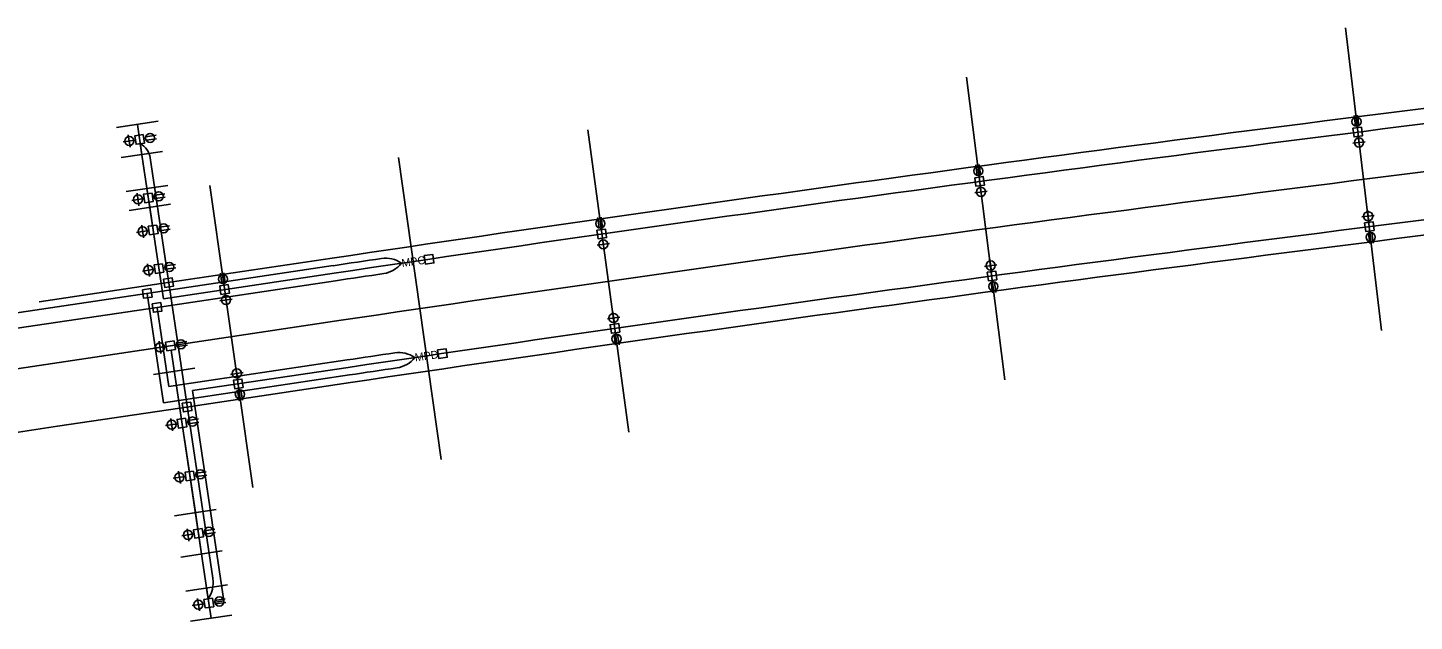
# Model space of a CAD drawing. Extents: x 927222 to 928611, y 636651 to 637029.
# Drawn here: x 927719.3 to 927901.3, y 636687 to 636764.9 of the extents above; entities that cross this region are included whole.
import ezdxf

# ---------------------------------------------------------------- set-up
doc = ezdxf.new("R2010")
doc.units = 0
for name, color, linetype in [('ActivePointCell_dp', 7, 'Continuous'), ('Miscellaneous2', 7, 'Continuous'), ('NonPlottingEle_dp', 7, 'Continuous'), ('PoleLight', 7, 'Continuous'), ('TextLabel', 7, 'Continuous')]:
    doc.layers.add(name, color=color, linetype=linetype)

msp = doc.modelspace()

# ---------------------------------------------------------------- linework, layer by layer
at = {"layer": 'ActivePointCell_dp'}
for p, q in [((927732.23, 636743.41), (927737.67, 636744.22)), ((927735.81, 636719.43), (927741.25, 636720.24)), ((927739.39, 636695.44), (927744.83, 636696.26))]:
    msp.add_line(p, q, dxfattribs=at)
at = {"layer": 'Miscellaneous2'}
for p, q in [((927896.95, 636725.18), (927892.24, 636764.9)), ((927847.53, 636718.73), (927842.5, 636758.41)), ((927730.97, 636751.82), (927736.41, 636752.63)), ((927734.29, 636748.27), (927733.69, 636752.22)), ((927798.17, 636711.86), (927792.81, 636751.5)), ((927731.57, 636747.86), (927737, 636748.67)), ((927773.54, 636708.27), (927767.96, 636747.88)), ((927735.32, 636741.35), (927734.95, 636743.82)), ((927748.86, 636704.6), (927743.19, 636744.19)), ((927732.6, 636740.94), (927738.04, 636741.75)), ((927735.32, 636741.35), (927736.2, 636735.41)), ((927738.03, 636723.17), (927760.44, 636726.52)), ((927738.03, 636723.17), (927760.44, 636726.52)), ((927641.76, 636708.8), (927738.03, 636723.17)), ((927641.76, 636708.8), (927738.03, 636723.17)), ((927741.3, 636701.29), (927739.86, 636710.93)), ((927738.58, 636700.88), (927744.02, 636701.7)), ((927742.11, 636695.85), (927741.3, 636701.29)), ((927740.06, 636690.99), (927745.5, 636691.81)), ((927743.37, 636687.44), (927742.78, 636691.4)), ((927740.65, 636687.04), (927746.09, 636687.85))]:
    msp.add_line(p, q, dxfattribs=at)
msp.add_arc((928647.64, 630784.89), 6007.5, 96.980509, 98.492547, dxfattribs=at)
msp.add_arc((928647.64, 630784.89), 6007.5, 96.980509, 98.492547, dxfattribs=at)
at = {"layer": 'NonPlottingEle_dp'}
for p, q in [((927734.07, 636749.69), (927737.11, 636729.35)), ((927735.36, 636747.85), (927743.6, 636692.67)), ((927736.81, 636731.33), (927759.23, 636734.68)), ((927736.96, 636730.34), (927759.37, 636733.69)), ((927737.11, 636729.35), (927759.52, 636732.7)), ((927720.79, 636728.94), (927736.81, 636731.33)), ((927736.27, 636728.22), (927759.67, 636731.71)), ((927640.69, 636715.97), (927736.96, 636730.34)), ((927734.98, 636730.05), (927737.13, 636715.71)), ((927640.98, 636713.99), (927736.27, 636728.22)), ((927736.27, 636728.22), (927737.82, 636717.83)), ((927738.12, 636722.62), (927742.99, 636689.98)), ((927737.82, 636717.83), (927761.22, 636721.33)), ((927740.93, 636717.29), (927761.37, 636720.34)), ((927737.13, 636715.71), (927761.51, 636719.35)), ((927739.25, 636715.01), (927761.66, 636718.36)), ((927740.93, 636717.29), (927745.05, 636689.72)), ((927723.22, 636712.62), (927739.25, 636715.01)), ((927642.98, 636700.64), (927723.22, 636712.62)), ((927743.63, 636689.5), (927745.05, 636689.72))]:
    msp.add_line(p, q, dxfattribs=at)
for centre, radius, start, end in [((928647.64, 630784.89), 6015.75, 96.980509, 98.492547), ((928647.64, 630784.89), 6013.75, 96.980509, 98.492547), ((927732.87, 636747.48), 2.52, 8.4925, 61.3837), ((928647.64, 630784.89), 6001.25, 96.980509, 98.492547), ((928647.64, 630784.89), 5999.25, 96.980509, 98.492547), ((928647.64, 630784.89), 6014.75, 98.431328, 98.492547), ((927766.26, 636731.03), 3.64, 54.9427, 98.4313), ((928647.64, 630784.89), 6012.75, 98.431325, 98.492547), ((927765.49, 636736.26), 3.64, 278.4313, 321.9148), ((928647.64, 630784.89), 6002.25, 98.432344, 98.492547), ((927768.01, 636718.65), 3.64, 54.9427, 98.6782), ((927767.23, 636723.88), 3.64, 278.4322, 321.9148), ((928647.64, 630784.89), 6000.25, 98.432192, 98.492547), ((927739.84, 636692.1), 3.8, 325.9435, 8.4925)]:
    msp.add_arc(centre, radius, start, end, dxfattribs=at)
at = {"layer": 'PoleLight'}
for p, q in [((927893.35, 636753.38), (927893.52, 636752.02)), ((927893.8, 636753.44), (927893.96, 636752.07)), ((927732.5, 636750.85), (927732.74, 636749.23)), ((927736.14, 636750.79), (927734.78, 636750.59)), ((927893.77, 636751.78), (927893.74, 636752)), ((927893.91, 636750.66), (927894.11, 636749.03)), ((927733.43, 636750.16), (927731.81, 636749.92)), ((927734.55, 636750.33), (927734.77, 636750.36)), ((927736.2, 636750.35), (927734.85, 636750.15)), ((927893.19, 636749.75), (927894.82, 636749.95)), ((927843.7, 636746.9), (927843.88, 636745.53)), ((927844.14, 636745.3), (927844.11, 636745.52)), ((927844.15, 636746.96), (927844.33, 636745.59)), ((927843.57, 636743.26), (927845.2, 636743.47)), ((927844.28, 636744.18), (927844.49, 636742.55)), ((927734.58, 636742.5), (927732.95, 636742.26)), ((927733.64, 636743.19), (927733.89, 636741.56)), ((927735.69, 636742.66), (927735.91, 636742.7)), ((927737.28, 636743.13), (927735.92, 636742.93)), ((927737.35, 636742.68), (927735.99, 636742.48)), ((927794.11, 636740), (927794.3, 636738.64)), ((927794.55, 636740.06), (927794.74, 636738.7)), ((927896.01, 636740.28), (927894.38, 636740.08)), ((927895.3, 636739.36), (927895.1, 636740.99)), ((927735.21, 636738.3), (927733.58, 636738.05)), ((927734.27, 636738.99), (927734.51, 636737.36)), ((927736.32, 636738.46), (927736.54, 636738.49)), ((927737.91, 636738.93), (927736.55, 636738.72)), ((927737.98, 636738.48), (927736.62, 636738.28)), ((927794.56, 636738.4), (927794.53, 636738.63)), ((927895.41, 636736.59), (927895.25, 636737.95)), ((927895.44, 636738.25), (927895.46, 636738.02)), ((927895.86, 636736.64), (927895.69, 636738.01)), ((927794.01, 636736.36), (927795.64, 636736.59)), ((927794.71, 636737.29), (927794.94, 636735.66)), ((927845.77, 636732.9), (927845.55, 636734.53)), ((927735.96, 636733.23), (927734.34, 636732.98)), ((927735.03, 636733.92), (927735.27, 636732.29)), ((927737.08, 636733.39), (927737.3, 636733.43)), ((927738.67, 636733.86), (927737.31, 636733.65)), ((927738.73, 636733.41), (927737.37, 636733.21)), ((927744.58, 636732.71), (927744.78, 636731.35)), ((927745.03, 636732.77), (927745.23, 636731.41)), ((927846.47, 636733.82), (927844.84, 636733.6)), ((927745.04, 636731.11), (927745.01, 636731.34)), ((927845.91, 636730.12), (927845.73, 636731.48)), ((927845.91, 636731.78), (927845.94, 636731.56)), ((927846.35, 636730.18), (927846.17, 636731.54)), ((927744.51, 636729.07), (927746.14, 636729.31)), ((927745.21, 636730), (927745.44, 636728.37)), ((927796.29, 636726.02), (927796.06, 636727.64)), ((927796.99, 636726.94), (927795.36, 636726.72)), ((927736.54, 636723.78), (927736.78, 636722.15)), ((927740.18, 636723.72), (927738.82, 636723.52)), ((927796.45, 636723.24), (927796.26, 636724.6)), ((927796.45, 636724.9), (927796.48, 636724.68)), ((927796.9, 636723.31), (927796.71, 636724.67)), ((927737.48, 636723.09), (927735.85, 636722.85)), ((927738.59, 636723.25), (927738.81, 636723.29)), ((927740.25, 636723.27), (927738.89, 636723.07)), ((927746.86, 636718.74), (927746.62, 636720.37)), ((927747.55, 636719.67), (927745.92, 636719.43)), ((927747.04, 636715.97), (927746.84, 636717.33)), ((927747.02, 636717.63), (927747.05, 636717.4)), ((927747.48, 636716.03), (927747.28, 636717.39)), ((927738.99, 636712.95), (927737.36, 636712.71)), ((927738.06, 636713.64), (927738.3, 636712.02)), ((927740.1, 636713.12), (927740.33, 636713.15)), ((927741.69, 636713.58), (927740.34, 636713.38)), ((927741.76, 636713.14), (927740.4, 636712.93)), ((927740.02, 636706.03), (927738.4, 636705.79)), ((927739.09, 636706.72), (927739.33, 636705.09)), ((927741.14, 636706.19), (927741.36, 636706.23)), ((927742.73, 636706.66), (927741.37, 636706.46)), ((927742.79, 636706.21), (927741.44, 636706.01)), ((927741.15, 636698.49), (927739.52, 636698.24)), ((927740.22, 636699.18), (927740.46, 636697.55)), ((927742.26, 636698.65), (927742.48, 636698.69)), ((927743.85, 636699.12), (927742.5, 636698.91)), ((927743.92, 636698.67), (927742.56, 636698.47)), ((927742.52, 636689.34), (927740.89, 636689.1)), ((927741.58, 636690.03), (927741.82, 636688.4)), ((927743.63, 636689.5), (927743.85, 636689.54)), ((927745.22, 636689.97), (927743.86, 636689.77)), ((927745.29, 636689.52), (927743.93, 636689.32))]:
    msp.add_line(p, q, dxfattribs=at)
for centre in [(927893.67, 636752.59), (927732.62, 636750.04), (927735.36, 636750.45), (927894.01, 636749.85), (927844.03, 636746.11), (927736.5, 636742.79), (927844.39, 636743.37), (927733.77, 636742.38), (927794.44, 636739.22), (927895.2, 636740.18), (927734.39, 636738.17), (927737.13, 636738.58), (927895.54, 636737.43), (927794.82, 636736.48), (927845.66, 636733.71), (927735.15, 636733.1), (927737.89, 636733.51), (927744.93, 636731.93), (927846.02, 636730.97), (927745.33, 636729.19), (927796.17, 636726.83), (927736.66, 636722.97), (927739.4, 636723.38), (927796.56, 636724.09), (927746.74, 636719.55), (927747.14, 636716.81), (927738.18, 636712.83), (927740.92, 636713.24), (927739.21, 636705.91), (927741.95, 636706.32), (927740.34, 636698.37), (927743.07, 636698.77), (927741.7, 636689.22), (927744.44, 636689.63)]:
    msp.add_circle(centre, 0.597, dxfattribs=at)
at = {"layer": 'TextLabel'}
for points in [[(927734.46, 636750.89), (927734.63, 636749.77), (927733.52, 636749.61), (927733.35, 636750.72)], [(927893.21, 636751.71), (927894.33, 636751.85), (927894.47, 636750.73), (927893.35, 636750.59)], [(927843.58, 636745.22), (927844.69, 636745.37), (927844.84, 636744.25), (927843.72, 636744.11)], [(927735.61, 636743.22), (927735.77, 636742.11), (927734.66, 636741.94), (927734.49, 636743.05)], [(927736.24, 636739.02), (927736.4, 636737.9), (927735.29, 636737.74), (927735.12, 636738.85)], [(927794, 636738.33), (927795.11, 636738.48), (927795.27, 636737.37), (927794.15, 636737.21)], [(927895.99, 636738.32), (927894.88, 636738.18), (927894.74, 636739.29), (927895.86, 636739.43)], [(927771.34, 636735.02), (927772.45, 636735.17), (927772.61, 636734.06), (927771.49, 636733.9)], [(927736.99, 636733.95), (927737.16, 636732.84), (927736.05, 636732.67), (927735.88, 636733.78)], [(927846.47, 636731.85), (927845.36, 636731.71), (927845.21, 636732.82), (927846.32, 636732.97)], [(927734.35, 636730.53), (927735.46, 636730.68), (927735.62, 636729.57), (927734.51, 636729.41)], [(927737.13, 636731.94), (927738.25, 636732.1), (927738.41, 636730.99), (927737.29, 636730.83)], [(927744.49, 636731.03), (927745.6, 636731.2), (927745.76, 636730.08), (927744.65, 636729.92)], [(927735.63, 636728.7), (927736.75, 636728.85), (927736.9, 636727.74), (927735.79, 636727.58)], [(927797, 636724.98), (927795.89, 636724.82), (927795.73, 636725.94), (927796.85, 636726.09)], [(927738.51, 636723.81), (927738.67, 636722.7), (927737.56, 636722.53), (927737.39, 636723.65)], [(927773.08, 636722.64), (927774.19, 636722.79), (927774.35, 636721.68), (927773.23, 636721.52)], [(927747.58, 636717.71), (927746.46, 636717.55), (927746.3, 636718.66), (927747.41, 636718.82)], [(927739.57, 636715.63), (927740.69, 636715.78), (927740.84, 636714.67), (927739.73, 636714.51)], [(927740.02, 636713.67), (927740.19, 636712.56), (927739.07, 636712.39), (927738.91, 636713.51)], [(927741.05, 636706.75), (927741.22, 636705.64), (927740.11, 636705.47), (927739.94, 636706.58)], [(927742.18, 636699.21), (927742.35, 636698.1), (927741.23, 636697.93), (927741.07, 636699.04)], [(927743.55, 636690.06), (927743.71, 636688.95), (927742.6, 636688.78), (927742.43, 636689.89)]]:
    msp.add_lwpolyline(points, close=True, dxfattribs=at)

# ---------------------------------------------------------------- texts
at = {"layer": 'PoleLight'}
for s, p in [('MPC', (927768.43, 636733.5)), ('MPD', (927770.17, 636721.12))]:
    msp.add_text(s, height=1.05, rotation=8.015, dxfattribs=at).set_placement(p)

doc.saveas('drawing.dxf')
